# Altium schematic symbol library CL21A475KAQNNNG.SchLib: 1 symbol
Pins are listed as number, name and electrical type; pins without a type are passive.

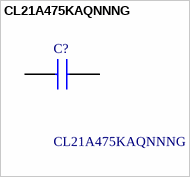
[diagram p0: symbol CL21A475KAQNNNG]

## CL21A475KAQNNNG
designator C?
Samsung Electro-Mechanics 0805 CL 4.7uF Ceramic Multilayer Capacitor, 25 V, +85C, X5R Dielectric, +/-10% SMD; Geometry.Height: 1.4mm
footprint CAPC2012X140N
pins: 1, 2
